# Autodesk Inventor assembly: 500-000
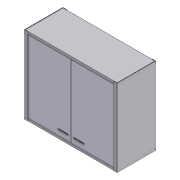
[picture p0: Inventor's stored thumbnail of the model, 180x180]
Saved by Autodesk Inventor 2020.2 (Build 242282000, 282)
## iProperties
Created: 2010-10
Part Number: 500-000
Document SubType Name: Assembly
Designer: F.Stasiak
Description: =Szafka sterownicza S:<d26> x W:<d27>
Company: Fabian Stasiak CAD Consulting
Manager: www.cadconsulting.pl
d26: 1200
d27: 1000
Author: F.Stasiak
Subject: Zbiór ćwiczeń. Autodesk Inventor 2020. Kurs podstawowy
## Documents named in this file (6)
- C:\2020_Kurs_podstawowy\R9 Zarządzanie plikami\500-000\500-000.iam
- C:\2020_Kurs_podstawowy\R9 Zarządzanie plikami\500-000\500-100.ipt
- C:\2020_Kurs_podstawowy\R9 Zarządzanie plikami\500-000\500-200.ipt
- C:\2020_Kurs_podstawowy\R9 Zarządzanie plikami\500-000\500-300.ipt
- C:\2020_Kurs_podstawowy\R9 Zarządzanie plikami\500-000\500-400.ipt
- C:\2020_Kurs_podstawowy\R9 Zarządzanie plikami\500-000\500-500.ipt
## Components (6 placed, 5 different names)
1. 500-100:1 — Zestawiający:1, Zestawiający:2, Równoległy:5, Równoległy:6, Zestawiający:3, Zestawiający:6, Zestawiający:9
2. 500-200:1 — Równoległy:4, Zestawiający:1, Równoległy:5, Równoległy:7, Zestawiający:7, Równoległy:8
3. 500-300:1 — Równoległy:4, Zestawiający:2, Równoległy:6, Zestawiający:3, Zestawiający:4, Zestawiający:5, Zestawiający:10
4. 500-400:1 — Równoległy:7, Zestawiający:4, Zestawiający:5, Zestawiający:8
5. 500-500:1 — Zestawiający:6, Zestawiający:7, Równoległy:8, Zestawiający:8, Równoległy:9
6. 500-500:2 — Zestawiający:9, Zestawiający:10, Równoległy:9
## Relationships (16: Mate 10, Flush 6)
- Równoległy:4 [Flush]: 500-200:1 ↔ 500-300:1
- Zestawiający:1 [Mate]: 500-100:1 ↔ 500-200:1
- Zestawiający:2 [Mate]: 500-100:1 ↔ 500-300:1
- Równoległy:5 [Flush]: 500-100:1 ↔ 500-200:1
- Równoległy:6 [Flush]: 500-100:1 ↔ 500-300:1
- Zestawiający:3 [Mate]: 500-100:1 ↔ 500-300:1
- Równoległy:7 [Flush]: 500-200:1 ↔ 500-400:1
- Zestawiający:4 [Mate]: 500-300:1 ↔ 500-400:1
- Zestawiający:5 [Mate]: 500-300:1 ↔ 500-400:1
- Zestawiający:6 [Mate]: 500-100:1 ↔ 500-500:1
- Zestawiający:7 [Mate]: 500-200:1 ↔ 500-500:1
- Równoległy:8 [Flush]: 500-200:1 ↔ 500-500:1
- Zestawiający:8 [Mate]: 500-400:1 ↔ 500-500:1
- Zestawiający:9 [Mate]: 500-100:1 ↔ 500-500:2
- Zestawiający:10 [Mate]: 500-300:1 ↔ 500-500:2
- Równoległy:9 [Flush]: 500-500:1 ↔ 500-500:2
